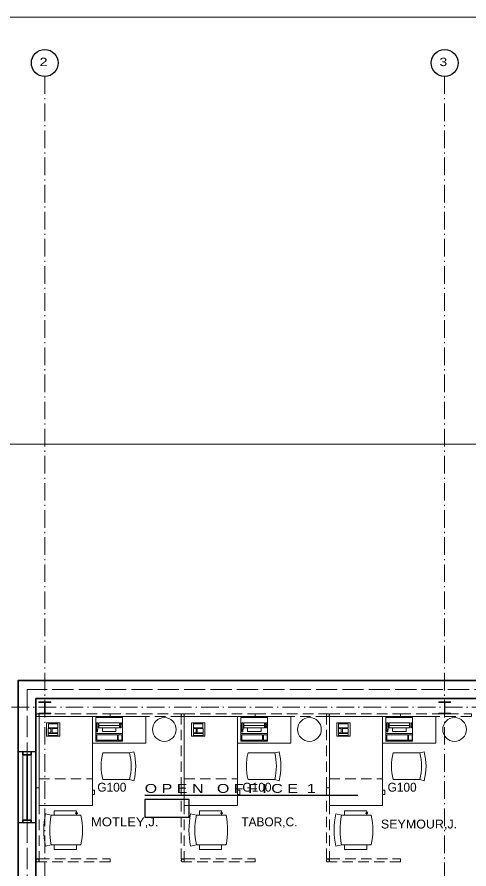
# Model space of a CAD drawing. Extents: x -118748 to -117136, y -118748 to -117596.
# Drawn here: x -118506.9 to -118262.8, y -118056 to -117596.4 of the extents above; entities that cross this region are included whole.
import ezdxf
from ezdxf.enums import TextEntityAlignment as Align

# ---------------------------------------------------------------- set-up
doc = ezdxf.new("R2010")
doc.units = 0
doc.header["$LTSCALE"] = 1.9
doc.header["$PDMODE"] = 32
doc.header["$PDSIZE"] = 0.95
for name, pattern in [('DOT_DASHED', [7.7, 5, -1.2, 0.3, -1.2]), ('LONG_DASHED', [7.5, 6, -1.5]), ('MEDIUM_DASHED', [4.5, 3, -1.5])]:
    doc.linetypes.add(name, pattern=pattern)
for name, color, linetype, lineweight in [('10', 7, 'DOT_DASHED', 13), ('11', 7, 'Continuous', 25), ('12', 7, 'Continuous', 13), ('15', 7, 'Continuous', 13), ('16', 7, 'Continuous', 13), ('17', 7, 'Continuous', 25), ('2', 7, 'Continuous', 35), ('20', 7, 'MEDIUM_DASHED', 13), ('23', 7, 'Continuous', 25), ('3', 7, 'Continuous', 35), ('30', 7, 'Continuous', 13), ('4', 7, 'Continuous', 35), ('45', 7, 'Continuous', 25), ('5', 7, 'Continuous', 13), ('6', 7, 'Continuous', 13), ('60', 7, 'LONG_DASHED', 13), ('9', 7, 'Continuous', 35)]:
    doc.layers.add(name, color=color, linetype=linetype, lineweight=lineweight)
doc.layers.add('53', color=7, linetype='Continuous')

msp = doc.modelspace()

# ---------------------------------------------------------------- linework, layer by layer
at = {"layer": '10'}
for p, q in [((-118491.921, -117628.339), (-118491.921, -118698.41)), ((-118275.921, -117628.339), (-118275.921, -118698.41)), ((-118641.571, -117968.81), (-117285.521, -117968.81))]:
    msp.add_line(p, q, dxfattribs=at)
at = {"layer": '11'}
for centre in [(-118491.921, -117621.139), (-118275.921, -117621.139)]:
    msp.add_circle(centre, 7.253, dxfattribs=at)
at = {"layer": '12'}
for points in [[(-118495.104, -117972.362), (-118488.688, -117972.362), (-118488.688, -117971.966), (-118491.772, -117971.966), (-118491.772, -117966.262), (-118488.688, -117966.262), (-118488.688, -117965.866), (-118495.104, -117965.866), (-118495.104, -117966.262), (-118492.02, -117966.262), (-118492.02, -117971.966), (-118495.104, -117971.966)], [(-118279.104, -117972.362), (-118272.688, -117972.362), (-118272.688, -117971.966), (-118275.772, -117971.966), (-118275.772, -117966.262), (-118272.688, -117966.262), (-118272.688, -117965.866), (-118279.104, -117965.866), (-118279.104, -117966.262), (-118276.02, -117966.262), (-118276.02, -117971.966), (-118279.104, -117971.966)]]:
    msp.add_lwpolyline(points, close=True, dxfattribs=at)
at = {"layer": '15', "lineweight": 25}
for p, q in [((-118098.321, -117954.41), (-118506.321, -117954.41)), ((-118506.321, -117954.41), (-118506.321, -117992.81)), ((-118496.721, -117992.81), (-118506.321, -117992.81)), ((-118496.721, -118031.21), (-118506.321, -118031.21)), ((-118506.321, -118031.21), (-118506.321, -118069.61)), ((-118496.721, -118031.21), (-118496.721, -118069.61))]:
    msp.add_line(p, q, dxfattribs=at)
at = {"layer": '15'}
for p, q in [((-118460.526, -117993.398), (-118446.126, -117993.398)), ((-118460.526, -117993.398), (-118446.126, -117993.398)), ((-118446.126, -117993.398), (-118443.804, -117992.791)), ((-118446.126, -117993.398), (-118443.804, -117992.791)), ((-118382.126, -117993.398), (-118367.726, -117993.398)), ((-118367.726, -117993.398), (-118365.404, -117992.791)), ((-118303.726, -117993.398), (-118289.326, -117993.398)), ((-118289.326, -117993.398), (-118287.004, -117992.791)), ((-118446.126, -118007.798), (-118460.526, -118007.798)), ((-118446.126, -118007.798), (-118460.526, -118007.798)), ((-118446.126, -118007.798), (-118443.804, -118008.404)), ((-118446.126, -118007.798), (-118443.804, -118008.404)), ((-118367.726, -118007.798), (-118382.126, -118007.798)), ((-118367.726, -118007.798), (-118365.404, -118008.404)), ((-118289.326, -118007.798), (-118303.726, -118007.798)), ((-118289.326, -118007.798), (-118287.004, -118008.404)), ((-118488.399, -118027.04), (-118491.527, -118026.364)), ((-118488.399, -118027.04), (-118491.527, -118026.364)), ((-118472.399, -118027.04), (-118488.399, -118027.04)), ((-118472.399, -118027.04), (-118488.399, -118027.04)), ((-118474.799, -118024.64), (-118486.799, -118024.64)), ((-118486.799, -118024.64), (-118486.799, -118027.04)), ((-118474.799, -118024.64), (-118486.799, -118024.64)), ((-118486.799, -118024.64), (-118486.799, -118027.04)), ((-118474.799, -118027.04), (-118486.799, -118027.04)), ((-118474.799, -118027.04), (-118486.799, -118027.04)), ((-118474.799, -118027.04), (-118474.799, -118024.64)), ((-118474.799, -118027.04), (-118474.799, -118024.64)), ((-118409.999, -118027.04), (-118413.126, -118026.364)), ((-118393.999, -118027.04), (-118409.999, -118027.04)), ((-118396.399, -118024.64), (-118408.399, -118024.64)), ((-118408.399, -118024.64), (-118408.399, -118027.04)), ((-118396.399, -118027.04), (-118408.399, -118027.04)), ((-118396.399, -118027.04), (-118396.399, -118024.64)), ((-118331.599, -118027.04), (-118334.727, -118026.364)), ((-118315.599, -118027.04), (-118331.599, -118027.04)), ((-118317.999, -118024.64), (-118329.999, -118024.64)), ((-118329.999, -118024.64), (-118329.999, -118027.04)), ((-118317.999, -118027.04), (-118329.999, -118027.04)), ((-118317.999, -118027.04), (-118317.999, -118024.64)), ((-118488.399, -118043.04), (-118491.527, -118043.716)), ((-118488.399, -118043.04), (-118491.527, -118043.716)), ((-118472.399, -118043.04), (-118488.399, -118043.04)), ((-118472.399, -118043.04), (-118488.399, -118043.04)), ((-118474.799, -118043.04), (-118486.799, -118043.04)), ((-118486.799, -118043.04), (-118486.799, -118045.44)), ((-118474.799, -118043.04), (-118486.799, -118043.04)), ((-118486.799, -118043.04), (-118486.799, -118045.44)), ((-118474.799, -118045.44), (-118486.799, -118045.44)), ((-118474.799, -118045.44), (-118486.799, -118045.44)), ((-118474.799, -118045.44), (-118474.799, -118043.04)), ((-118474.799, -118045.44), (-118474.799, -118043.04)), ((-118409.999, -118043.04), (-118413.126, -118043.716)), ((-118393.999, -118043.04), (-118409.999, -118043.04)), ((-118396.399, -118043.04), (-118408.399, -118043.04)), ((-118408.399, -118043.04), (-118408.399, -118045.44)), ((-118396.399, -118045.44), (-118408.399, -118045.44)), ((-118396.399, -118045.44), (-118396.399, -118043.04)), ((-118331.599, -118043.04), (-118334.727, -118043.716)), ((-118315.599, -118043.04), (-118331.599, -118043.04)), ((-118317.999, -118043.04), (-118329.999, -118043.04)), ((-118329.999, -118043.04), (-118329.999, -118045.44)), ((-118317.999, -118045.44), (-118329.999, -118045.44)), ((-118317.999, -118045.44), (-118317.999, -118043.04))]:
    msp.add_line(p, q, dxfattribs=at)
at = {"layer": '15', "lineweight": 25}
msp.add_lwpolyline([(-118098.321, -117964.01), (-118496.721, -117964.01), (-118496.721, -117992.81)], dxfattribs=at)
at = {"layer": '15'}
for points in [[(-118495.012, -118021.839), (-118466.212, -118021.839), (-118466.212, -117973.839), (-118495.012, -117973.839)], [(-118495.012, -118021.839), (-118466.212, -118021.839), (-118466.212, -117973.839), (-118495.012, -117973.839)], [(-118466.212, -117988.239), (-118437.412, -117988.239), (-118437.412, -117973.839), (-118466.212, -117973.839)], [(-118466.212, -117988.239), (-118437.412, -117988.239), (-118437.412, -117973.839), (-118466.212, -117973.839)], [(-118416.612, -118021.839), (-118387.812, -118021.839), (-118387.812, -117973.839), (-118416.612, -117973.839)], [(-118387.812, -117988.239), (-118359.012, -117988.239), (-118359.012, -117973.839), (-118387.812, -117973.839)], [(-118338.212, -118021.839), (-118309.412, -118021.839), (-118309.412, -117973.839), (-118338.212, -117973.839)], [(-118309.412, -117988.239), (-118280.612, -117988.239), (-118280.612, -117973.839), (-118309.412, -117973.839)]]:
    msp.add_lwpolyline(points, close=True, dxfattribs=at)
for centre, radius, start, end in [((-118432.976, -118000.597), 28.475, 165.35367, 194.64632), ((-118432.976, -118000.597), 28.475, 165.35367, 194.64632), ((-118473.675, -118000.597), 28.475, 345.35367, 14.64632), ((-118473.675, -118000.597), 28.475, 345.35367, 14.64632), ((-118473.675, -118000.597), 30.875, 345.35367, 14.64632), ((-118473.675, -118000.597), 30.875, 345.35367, 14.64632), ((-118354.576, -118000.597), 28.475, 165.35367, 194.64632), ((-118395.275, -118000.597), 28.475, 345.35367, 14.64632), ((-118395.275, -118000.597), 30.875, 345.35367, 14.64632), ((-118276.176, -118000.597), 28.475, 165.35367, 194.64632), ((-118316.875, -118000.597), 28.475, 345.35367, 14.64632), ((-118316.875, -118000.597), 30.875, 345.35367, 14.64632), ((-118451.39, -118035.04), 41.063, 167.80217, 192.19782), ((-118451.39, -118035.04), 41.063, 167.80217, 192.19782), ((-118451.39, -118035.04), 37.863, 167.80217, 192.19782), ((-118451.39, -118035.04), 37.863, 167.80217, 192.19782), ((-118451.39, -118035.04), 37.863, 167.80217, 192.19782), ((-118451.39, -118035.04), 37.863, 167.80217, 192.19782), ((-118509.407, -118035.04), 37.863, 347.80217, 12.19783), ((-118509.407, -118035.04), 37.863, 347.80217, 12.19783), ((-118372.99, -118035.04), 41.063, 167.80217, 192.19782), ((-118372.99, -118035.04), 37.863, 167.80217, 192.19782), ((-118372.99, -118035.04), 37.863, 167.80217, 192.19782), ((-118431.007, -118035.04), 37.863, 347.80217, 12.19783), ((-118294.59, -118035.04), 41.063, 167.80217, 192.19782), ((-118294.59, -118035.04), 37.863, 167.80217, 192.19782), ((-118294.59, -118035.04), 37.863, 167.80217, 192.19782), ((-118352.607, -118035.04), 37.863, 347.80217, 12.19783)]:
    msp.add_arc(centre, radius, start, end, dxfattribs=at)
for p in [(-118474.799, -118025.84), (-118396.399, -118025.84), (-118317.999, -118025.84)]:
    msp.add_point(p, dxfattribs=at)
at = {"layer": '16'}
for p, q in [((-118464.415, -117983.025), (-118450.015, -117983.025)), ((-118464.415, -117983.025), (-118450.015, -117983.025)), ((-118386.015, -117983.025), (-118371.615, -117983.025)), ((-118307.615, -117983.025), (-118293.215, -117983.025)), ((-118506.321, -118031.21), (-118506.321, -117992.81)), ((-118503.703, -118029.61), (-118503.703, -117994.41)), ((-118499.339, -117994.41), (-118499.339, -118029.61)), ((-118496.721, -117992.81), (-118496.721, -118031.21))]:
    msp.add_line(p, q, dxfattribs=at)
at = {"layer": '16', "lineweight": 35}
msp.add_line((-118501.521, -118029.61), (-118501.521, -117994.41), dxfattribs=at)
at = {"layer": '16'}
for points in [[(-118464.415, -117987.025), (-118464.415, -117974.225), (-118450.015, -117974.225), (-118450.015, -117987.025)], [(-118464.415, -117987.025), (-118464.415, -117974.225), (-118450.015, -117974.225), (-118450.015, -117987.025)], [(-118386.015, -117987.025), (-118386.015, -117974.225), (-118371.615, -117974.225), (-118371.615, -117987.025)], [(-118307.615, -117987.025), (-118307.615, -117974.225), (-118293.215, -117974.225), (-118293.215, -117987.025)], [(-118483.827, -117984.461), (-118491.027, -117984.461), (-118491.027, -117977.261), (-118483.827, -117977.261)], [(-118483.827, -117984.461), (-118491.027, -117984.461), (-118491.027, -117977.261), (-118483.827, -117977.261)], [(-118490.076, -117982.505), (-118488.62, -117982.505), (-118488.62, -117980.216), (-118490.076, -117980.216)], [(-118490.076, -117982.505), (-118488.62, -117982.505), (-118488.62, -117980.216), (-118490.076, -117980.216)], [(-118489.993, -117979.842), (-118484.875, -117979.842), (-118484.875, -117977.637), (-118489.993, -117977.637)], [(-118489.993, -117979.842), (-118484.875, -117979.842), (-118484.875, -117977.637), (-118489.993, -117977.637)], [(-118487.954, -117982.588), (-118484.834, -117982.588), (-118484.834, -117980.299), (-118487.954, -117980.299)], [(-118487.954, -117982.588), (-118484.834, -117982.588), (-118484.834, -117980.299), (-118487.954, -117980.299)], [(-118464.041, -117981.99), (-118464.041, -117981.158), (-118463.375, -117981.158), (-118463.375, -117981.99)], [(-118464.041, -117981.99), (-118464.041, -117981.158), (-118463.375, -117981.158), (-118463.375, -117981.99)], [(-118463.957, -117980.742), (-118463.957, -117977.206), (-118463.25, -117977.206), (-118463.25, -117980.742)], [(-118463.957, -117980.742), (-118463.957, -117977.206), (-118463.25, -117977.206), (-118463.25, -117980.742)], [(-118462.751, -117978.704), (-118462.751, -117977.104), (-118451.642, -117977.104), (-118451.642, -117978.704)], [(-118462.751, -117978.704), (-118462.751, -117977.104), (-118451.642, -117977.104), (-118451.642, -117978.704)], [(-118462.751, -117979.91), (-118462.751, -117978.704), (-118451.642, -117978.704), (-118451.642, -117979.91)], [(-118462.751, -117979.91), (-118462.751, -117978.704), (-118451.642, -117978.704), (-118451.642, -117979.91)], [(-118460.837, -117981.783), (-118460.837, -117979.91), (-118453.514, -117979.91), (-118453.514, -117981.783)], [(-118460.837, -117981.783), (-118460.837, -117979.91), (-118453.514, -117979.91), (-118453.514, -117981.783)], [(-118451.018, -117977.123), (-118451.018, -117978.121), (-118450.435, -117978.121), (-118450.435, -117977.123)], [(-118451.018, -117977.123), (-118451.018, -117978.121), (-118450.435, -117978.121), (-118450.435, -117977.123)], [(-118451.018, -117978.704), (-118451.018, -117979.952), (-118450.602, -117979.952), (-118450.602, -117978.704)], [(-118451.018, -117978.704), (-118451.018, -117979.952), (-118450.602, -117979.952), (-118450.602, -117978.704)], [(-118405.427, -117984.461), (-118412.627, -117984.461), (-118412.627, -117977.261), (-118405.427, -117977.261)], [(-118411.676, -117982.505), (-118410.22, -117982.505), (-118410.22, -117980.216), (-118411.676, -117980.216)], [(-118411.593, -117979.842), (-118406.475, -117979.842), (-118406.475, -117977.637), (-118411.593, -117977.637)], [(-118409.554, -117982.588), (-118406.434, -117982.588), (-118406.434, -117980.299), (-118409.554, -117980.299)], [(-118385.641, -117981.99), (-118385.641, -117981.158), (-118384.975, -117981.158), (-118384.975, -117981.99)], [(-118385.557, -117980.742), (-118385.557, -117977.206), (-118384.85, -117977.206), (-118384.85, -117980.742)], [(-118384.351, -117978.704), (-118384.351, -117977.104), (-118373.242, -117977.104), (-118373.242, -117978.704)], [(-118384.351, -117979.91), (-118384.351, -117978.704), (-118373.242, -117978.704), (-118373.242, -117979.91)], [(-118382.437, -117981.783), (-118382.437, -117979.91), (-118375.114, -117979.91), (-118375.114, -117981.783)], [(-118372.618, -117977.123), (-118372.618, -117978.121), (-118372.035, -117978.121), (-118372.035, -117977.123)], [(-118372.618, -117978.704), (-118372.618, -117979.952), (-118372.202, -117979.952), (-118372.202, -117978.704)], [(-118327.027, -117984.461), (-118334.227, -117984.461), (-118334.227, -117977.261), (-118327.027, -117977.261)], [(-118333.276, -117982.505), (-118331.82, -117982.505), (-118331.82, -117980.216), (-118333.276, -117980.216)], [(-118333.193, -117979.842), (-118328.075, -117979.842), (-118328.075, -117977.637), (-118333.193, -117977.637)], [(-118331.154, -117982.588), (-118328.034, -117982.588), (-118328.034, -117980.299), (-118331.154, -117980.299)], [(-118307.24, -117981.99), (-118307.24, -117981.158), (-118306.575, -117981.158), (-118306.575, -117981.99)], [(-118307.157, -117980.742), (-118307.157, -117977.206), (-118306.45, -117977.206), (-118306.45, -117980.742)], [(-118305.951, -117978.704), (-118305.951, -117977.104), (-118294.842, -117977.104), (-118294.842, -117978.704)], [(-118305.951, -117979.91), (-118305.951, -117978.704), (-118294.842, -117978.704), (-118294.842, -117979.91)], [(-118304.037, -117981.783), (-118304.037, -117979.91), (-118296.714, -117979.91), (-118296.714, -117981.783)], [(-118294.218, -117977.123), (-118294.218, -117978.121), (-118293.635, -117978.121), (-118293.635, -117977.123)], [(-118294.218, -117978.704), (-118294.218, -117979.952), (-118293.802, -117979.952), (-118293.802, -117978.704)], [(-118484.834, -117983.004), (-118490.076, -117983.004), (-118490.076, -117984.086), (-118484.834, -117984.086)], [(-118484.834, -117983.004), (-118490.076, -117983.004), (-118490.076, -117984.086), (-118484.834, -117984.086)], [(-118463.874, -117983.572), (-118463.874, -117986.567), (-118452.682, -117986.567), (-118452.682, -117983.572)], [(-118463.874, -117983.572), (-118463.874, -117986.567), (-118452.682, -117986.567), (-118452.682, -117983.572)], [(-118452.266, -117983.655), (-118452.266, -117986.609), (-118450.269, -117986.609), (-118450.269, -117983.655)], [(-118452.266, -117983.655), (-118452.266, -117986.609), (-118450.269, -117986.609), (-118450.269, -117983.655)], [(-118406.434, -117983.004), (-118411.676, -117983.004), (-118411.676, -117984.086), (-118406.434, -117984.086)], [(-118385.474, -117983.572), (-118385.474, -117986.567), (-118374.282, -117986.567), (-118374.282, -117983.572)], [(-118373.866, -117983.655), (-118373.866, -117986.609), (-118371.869, -117986.609), (-118371.869, -117983.655)], [(-118328.034, -117983.004), (-118333.276, -117983.004), (-118333.276, -117984.086), (-118328.034, -117984.086)], [(-118307.074, -117983.572), (-118307.074, -117986.567), (-118295.882, -117986.567), (-118295.882, -117983.572)], [(-118295.466, -117983.655), (-118295.466, -117986.609), (-118293.469, -117986.609), (-118293.469, -117983.655)]]:
    msp.add_lwpolyline(points, close=True, dxfattribs=at)
at = {"layer": '16', "lineweight": 35}
for points in [[(-118503.703, -117992.81), (-118503.703, -117994.41), (-118499.339, -117994.41), (-118499.339, -117992.81)], [(-118503.703, -118031.21), (-118503.703, -118029.61), (-118499.339, -118029.61), (-118499.339, -118031.21)]]:
    msp.add_lwpolyline(points, dxfattribs=at)
at = {"layer": '17'}
msp.add_line((-118437.959, -118016.168), (-118322.759, -118016.168), dxfattribs=at)
at = {"layer": '2', "lineweight": 13}
msp.add_lwpolyline([(-118748.365, -118748.365), (-117365.965, -118748.365), (-117365.965, -117826.765), (-118748.365, -117826.765), (-118748.365, -118748.365), (-117135.565, -118748.365), (-117135.565, -117596.365), (-118748.365, -117596.365)], close=True, dxfattribs=at)
at = {"layer": '20'}
for points in [[(-118495.012, -117973.839), (-118495.012, -117972.239), (-118456.612, -117972.239), (-118456.612, -117973.839)], [(-118495.012, -117973.839), (-118495.012, -117972.239), (-118456.612, -117972.239), (-118456.612, -117973.839)], [(-118456.612, -117973.839), (-118456.612, -117972.239), (-118418.212, -117972.239), (-118418.212, -117973.839)], [(-118456.612, -117973.839), (-118456.612, -117972.239), (-118418.212, -117972.239), (-118418.212, -117973.839)], [(-118416.612, -117973.839), (-118416.612, -117972.239), (-118378.212, -117972.239), (-118378.212, -117973.839)], [(-118378.212, -117973.839), (-118378.212, -117972.239), (-118339.812, -117972.239), (-118339.812, -117973.839)], [(-118338.212, -117973.839), (-118338.212, -117972.239), (-118299.812, -117972.239), (-118299.812, -117973.839)], [(-118299.812, -117973.839), (-118299.812, -117972.239), (-118261.412, -117972.239), (-118261.412, -117973.839)], [(-118496.612, -117973.839), (-118495.012, -117973.839), (-118495.012, -118012.239), (-118496.612, -118012.239)], [(-118496.612, -117973.839), (-118495.012, -117973.839), (-118495.012, -118012.239), (-118496.612, -118012.239)], [(-118418.212, -117973.839), (-118416.612, -117973.839), (-118416.612, -118012.239), (-118418.212, -118012.239)], [(-118418.212, -117973.839), (-118416.612, -117973.839), (-118416.612, -118012.239), (-118418.212, -118012.239)], [(-118418.212, -117973.839), (-118416.612, -117973.839), (-118416.612, -118012.239), (-118418.212, -118012.239)], [(-118339.812, -117973.839), (-118338.212, -117973.839), (-118338.212, -118012.239), (-118339.812, -118012.239)], [(-118339.812, -117973.839), (-118338.212, -117973.839), (-118338.212, -118012.239), (-118339.812, -118012.239)], [(-118496.612, -118012.239), (-118495.012, -118012.239), (-118495.012, -118050.639), (-118496.612, -118050.639)], [(-118496.612, -118012.239), (-118495.012, -118012.239), (-118495.012, -118050.639), (-118496.612, -118050.639)], [(-118418.212, -118012.239), (-118416.612, -118012.239), (-118416.612, -118050.639), (-118418.212, -118050.639)], [(-118418.212, -118012.239), (-118416.612, -118012.239), (-118416.612, -118050.639), (-118418.212, -118050.639)], [(-118418.212, -118012.239), (-118416.612, -118012.239), (-118416.612, -118050.639), (-118418.212, -118050.639)], [(-118339.812, -118012.239), (-118338.212, -118012.239), (-118338.212, -118050.639), (-118339.812, -118050.639)], [(-118339.812, -118012.239), (-118338.212, -118012.239), (-118338.212, -118050.639), (-118339.812, -118050.639)], [(-118495.012, -118052.239), (-118495.012, -118050.639), (-118456.612, -118050.639), (-118456.612, -118052.239)], [(-118495.012, -118052.239), (-118495.012, -118050.639), (-118456.612, -118050.639), (-118456.612, -118052.239)], [(-118416.612, -118052.239), (-118416.612, -118050.639), (-118378.212, -118050.639), (-118378.212, -118052.239)], [(-118338.212, -118052.239), (-118338.212, -118050.639), (-118299.812, -118050.639), (-118299.812, -118052.239)]]:
    msp.add_lwpolyline(points, close=True, dxfattribs=at)
for centre in [(-118495.812, -117973.039), (-118495.812, -117973.039), (-118417.412, -117973.039), (-118417.412, -117973.039), (-118417.412, -117973.039), (-118339.012, -117973.039), (-118339.012, -117973.039), (-118495.812, -118051.439), (-118495.812, -118051.439), (-118417.412, -118051.439), (-118339.012, -118051.439)]:
    msp.add_circle(centre, 0.8, dxfattribs=at)
at = {"layer": '23', "linetype": 'MEDIUM_DASHED', "lineweight": 13}
for points in [[(-118466.212, -118021.839), (-118495.012, -118021.839), (-118495.012, -118007.439), (-118466.212, -118007.439)], [(-118466.212, -118021.839), (-118495.012, -118021.839), (-118495.012, -118007.439), (-118466.212, -118007.439)], [(-118387.812, -118021.839), (-118416.612, -118021.839), (-118416.612, -118007.439), (-118387.812, -118007.439)], [(-118309.412, -118021.839), (-118338.212, -118021.839), (-118338.212, -118007.439), (-118309.412, -118007.439)], [(-118466.212, -118015.839), (-118465.012, -118015.839), (-118465.012, -118013.439), (-118466.212, -118013.439)], [(-118466.212, -118015.839), (-118465.012, -118015.839), (-118465.012, -118013.439), (-118466.212, -118013.439)], [(-118387.812, -118015.839), (-118386.612, -118015.839), (-118386.612, -118013.439), (-118387.812, -118013.439)], [(-118309.412, -118015.839), (-118308.212, -118015.839), (-118308.212, -118013.439), (-118309.412, -118013.439)]]:
    msp.add_lwpolyline(points, close=True, dxfattribs=at)
at = {"layer": '3'}
msp.add_lwpolyline([(-118595.921, -118352.81), (-118595.921, -118170.41), (-118506.321, -118170.41), (-118506.321, -117954.41), (-118098.321, -117954.41), (-117829.521, -117954.41)], dxfattribs=at)
at = {"layer": '30'}
for centre in [(-118427.363, -117980.776), (-118427.363, -117980.776), (-118348.963, -117980.776), (-118270.562, -117980.776)]:
    msp.add_circle(centre, 6.4, dxfattribs=at)
at = {"layer": '4'}
msp.add_lwpolyline([(-118496.721, -117964.01), (-118496.721, -118636.01), (-118271.121, -118636.01), (-118271.121, -118588.01), (-118115.969, -118588.01), (-118106.1, -118586.234), (-118096.66, -118581.314), (-118089.115, -118573.804), (-118084.156, -118564.399), (-118081.154, -118548.633), (-118079.134, -118548.633), (-117884.057, -118548.587), (-117881.646, -118565.336), (-117876.897, -118574.111), (-117869.271, -118581.538), (-117859.789, -118586.351), (-117850.271, -118588.01), (-117695.121, -118588.01), (-117695.121, -118636.01), (-117469.521, -118636.01), (-117469.521, -117964.01)], close=True, dxfattribs=at)
at = {"layer": '45'}
msp.add_lwpolyline([(-118437.959, -118018.568), (-118437.959, -118028.168), (-118413.959, -118028.168), (-118413.959, -118018.568)], close=True, dxfattribs=at)
at = {"layer": '5'}
msp.add_line((-118496.721, -117964.01), (-117986.969, -117964.01), dxfattribs=at)
for points in [[(-118115.969, -118588.01), (-118271.121, -118588.01), (-118271.121, -118636.01), (-118496.721, -118636.01), (-118496.721, -117964.01)], [(-118496.721, -117964.01), (-118098.321, -117964.01), (-117984.721, -117964.01), (-117984.721, -118118.36), (-118059.921, -118118.36)], [(-118126.371, -118184.81), (-118126.371, -118292.01), (-118463.121, -118292.01), (-118496.721, -118292.01), (-118496.721, -118180.01), (-118496.721, -117964.01)]]:
    msp.add_lwpolyline(points, dxfattribs=at)
at = {"layer": '6'}
for points in [[(-118126.371, -118184.81), (-118126.371, -118292.01), (-118496.721, -118292.01), (-118496.721, -117964.01)], [(-118496.721, -117964.01), (-117984.721, -117964.01), (-117984.721, -118118.36), (-118059.921, -118118.36)]]:
    msp.add_lwpolyline(points, dxfattribs=at)
at = {"layer": '60'}
for points in [[(-118501.521, -117959.21), (-118501.521, -118175.21), (-118591.121, -118175.21)], [(-117464.721, -118175.21), (-117464.721, -117959.21), (-118501.521, -117959.21)]]:
    msp.add_lwpolyline(points, dxfattribs=at)

# ---------------------------------------------------------------- texts
at = {"layer": '11'}
for s, width, p in [(' 2 ', 1.3, (-118492.601, -117622.84)), (' 3 ', 1.25, (-118276.654, -117622.84))]:
    msp.add_text(s, height=4.518, dxfattribs=dict(at, width=width)).set_placement(p, align=Align.CENTER)
at = {"layer": '17', "width": 1.35}
msp.add_text('O P E N   O F F I C E  1', height=4.8, dxfattribs=at).set_placement((-118437.959, -118014.968))
at = {"layer": '53'}
for s, width, p in [('MOTLEY,J.', 1.1, (-118467.011, -118033.014)), ('SEYMOUR,J.', 1.05, (-118310.395, -118034.191))]:
    msp.add_text(s, height=4.8, dxfattribs=dict(at, width=width)).set_placement(p)
msp.add_text('TABOR,C.', height=4.8, dxfattribs=at).set_placement((-118385.759, -118033.014))
at = {"layer": '9'}
for p in [(-118455.703, -118014.325), (-118377.303, -118014.325), (-118298.903, -118014.325)]:
    msp.add_text('G100', height=4.8, dxfattribs=at).set_placement(p, align=Align.CENTER)

doc.saveas('drawing.dxf')
